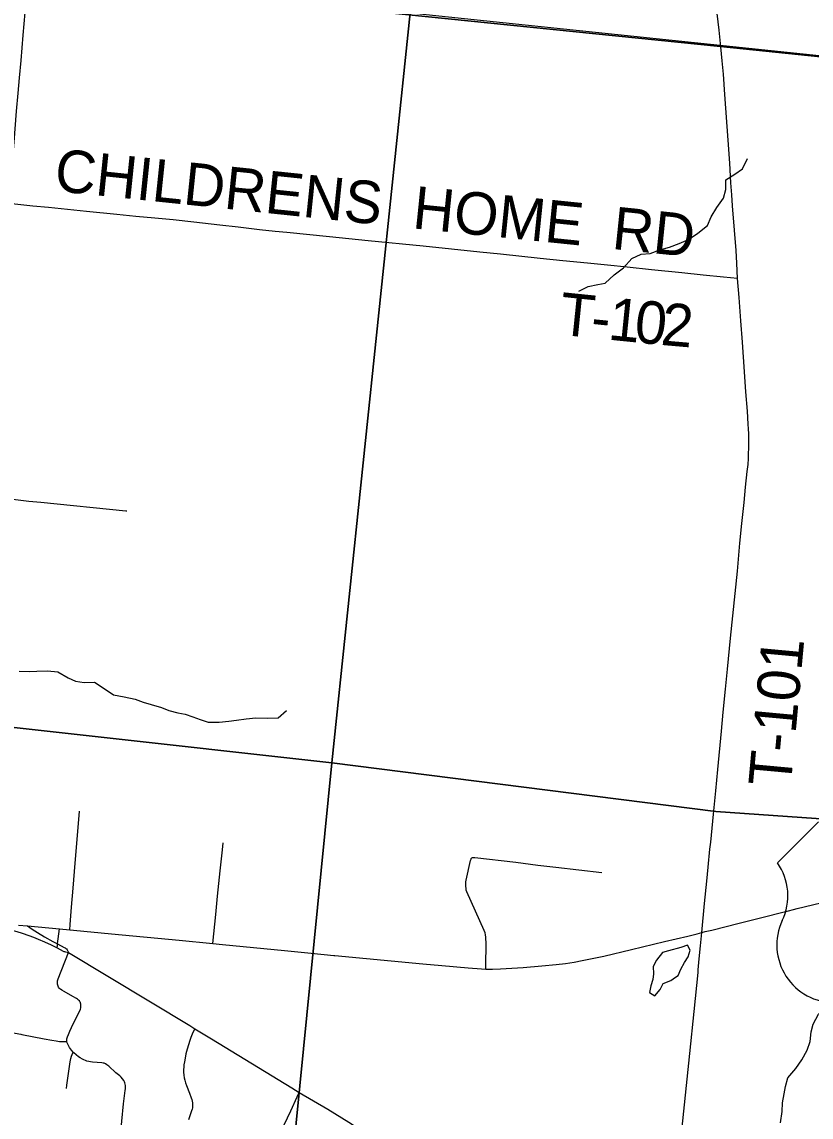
# Model space of a CAD drawing. Extents: x 0 to 1067, y 0 to 440.
# Drawn here: x 445.6 to 508.9, y 79.3 to 167.1 of the extents above; entities that cross this region are included whole.
import ezdxf

# ---------------------------------------------------------------- set-up
doc = ezdxf.new("R2010")
doc.units = 0
for name, color, linetype in [('GM_X_City_Street', 7, 'Continuous'), ('GM_X_Minor_Lake', 7, 'Continuous'), ('GM_X_Minor_River', 7, 'Continuous'), ('GM_X_Section', 7, 'Continuous'), ('GM_X_State_Route', 7, 'Continuous'), ('GM_X_Township_Road', 7, 'Continuous'), ('GM_X_Township_Road_Text', 7, 'Continuous'), ('GM_X_US_Route', 7, 'Continuous'), ('GM_X_US_Shield', 7, 'Continuous')]:
    doc.layers.add(name, color=color, linetype=linetype)

msp = doc.modelspace()

# ---------------------------------------------------------------- linework, layer by layer
at = {"layer": 'GM_X_City_Street'}
for points in [[(443.831, 125.541), (443.87, 125.958), (443.98, 127.147), (444.089, 128.111), (444.125, 128.52), (444.151, 128.63), (444.181, 128.697), (444.225, 128.757), (444.281, 128.805), (444.382, 128.851), (444.492, 128.862), (445.124, 128.802), (446.199, 128.688), (447.163, 128.585), (453.978, 127.908), (454.048, 127.901)], [(449.481, 94.317), (449.517, 94.753), (449.629, 96.127), (449.755, 97.649), (449.866, 98.986), (450.265, 103.821)], [(460.948, 93.213), (461.182, 95.554), (461.318, 97.004), (461.528, 99.046), (461.717, 100.716), (461.778, 101.284)], [(482.826, 91.173), (482.837, 91.669), (482.866, 92.972), (482.857, 93.361), (482.848, 93.552), (482.835, 93.733), (482.808, 93.914), (482.77, 94.066), (482.702, 94.25), (481.31, 97.348), (481.269, 97.492), (481.247, 97.633), (481.229, 97.823), (481.225, 97.987), (481.238, 98.15), (481.258, 98.293), (481.62, 99.866), (481.65, 99.972), (481.671, 100.032), (481.707, 100.083), (481.761, 100.112), (481.831, 100.123), (481.963, 100.113), (485.246, 99.742), (486.993, 99.498), (488.457, 99.335), (490.302, 99.13), (492.137, 98.913)], [(453.523, 77.598), (453.802, 80.367), (453.876, 80.996), (453.926, 81.438), (453.937, 81.577), (453.944, 81.759), (453.94, 81.849), (453.925, 81.954), (453.903, 82.05), (453.869, 82.14), (453.824, 82.225), (453.72, 82.369), (453.597, 82.509), (453.496, 82.601), (453.184, 82.859), (452.613, 83.382), (452.461, 83.492), (452.335, 83.574), (452.23, 83.615), (452.152, 83.634), (452.043, 83.65), (451.678, 83.677), (451.301, 83.702), (451.135, 83.723), (450.997, 83.753), (450.859, 83.794), (450.746, 83.834), (450.61, 83.894), (450.502, 83.945), (450.315, 84.051), (450.182, 84.145), (450.001, 84.283), (449.806, 84.456), (449.754, 84.518), (449.627, 84.664), (449.468, 84.886), (449.322, 85.138), (449.276, 85.249), (449.253, 85.365), (449.246, 85.477), (449.256, 85.568), (449.302, 85.734), (449.377, 85.931), (449.488, 86.204), (449.61, 86.482), (450.331, 87.955), (450.36, 88.052), (450.374, 88.159), (450.377, 88.294), (450.368, 88.369), (450.353, 88.428), (450.33, 88.495), (450.299, 88.546), (450.256, 88.618), (450.192, 88.685), (450.114, 88.748), (450.022, 88.811), (449.738, 88.975), (449.024, 89.369), (448.835, 89.488), (448.739, 89.55), (448.684, 89.594), (448.635, 89.643), (448.579, 89.721), (448.546, 89.795), (448.52, 89.873), (448.503, 89.961), (448.491, 90.081), (448.497, 90.172), (448.511, 90.238), (448.556, 90.387), (449.373, 92.511)], [(427.54, 87.969), (428.165, 87.921), (429.724, 87.787), (440.527, 86.741), (441.537, 86.636), (441.88, 86.594), (442.641, 86.476), (443.587, 86.308), (445.546, 85.942), (445.63, 85.926), (447.436, 85.576), (448.043, 85.462), (448.382, 85.406), (448.645, 85.376), (448.887, 85.355), (449.253, 85.365)], [(459.502, 86.39), (459.377, 86.14), (459.288, 85.945), (459.191, 85.695), (459.107, 85.432), (458.895, 84.756), (458.794, 84.367), (458.72, 84.016), (458.67, 83.739), (458.635, 83.493), (458.618, 83.295), (458.611, 83.122), (458.607, 82.909), (458.623, 82.676), (458.658, 82.455), (458.698, 82.258), (458.754, 82.057), (458.839, 81.835), (459.086, 81.21), (459.213, 80.861), (459.258, 80.717), (459.296, 80.568), (459.313, 80.453), (459.326, 80.312), (459.322, 80.168), (459.313, 80.048), (459.296, 79.951), (459.252, 79.798), (459.011, 79.093)], [(449.214, 81.604), (449.239, 81.857), (449.34, 82.611), (449.517, 83.741), (449.568, 84.004), (449.617, 84.182), (449.663, 84.315), (449.754, 84.518)], [(466.362, 78.057), (467.214, 79.797), (467.72, 80.916), (467.885, 81.28)]]:
    msp.add_lwpolyline(points, dxfattribs=at)
at = {"layer": 'GM_X_Minor_Lake'}
for points in [[(498.051, 90.518), (498.25, 90.646), (498.481, 91.167), (498.758, 91.688), (499.057, 92.141), (499.22, 92.686), (498.997, 93.097), (498.473, 92.896), (497.472, 92.631), (496.994, 92.499)], [(496.994, 92.499), (496.512, 91.888), (496.258, 91.367), (496.276, 90.798), (496.227, 90.343), (496.064, 89.821), (495.969, 89.299), (496.398, 89.023), (496.811, 89.542), (497.042, 90.018), (497.657, 90.264), (498.051, 90.518)]]:
    msp.add_lwpolyline(points, dxfattribs=at)
at = {"layer": 'GM_X_Minor_River'}
for points in [[(490.28, 145.516), (491.033, 145.896), (491.806, 146.05), (492.397, 146.158), (493.129, 146.812), (493.86, 147.375), (494.547, 148.121), (495.299, 148.479), (496.003, 148.518), (496.777, 148.831), (497.551, 149.029), (498.325, 149.342), (499.077, 149.654), (499.83, 150.171), (500.607, 150.779), (500.908, 151.482), (501.345, 152.229), (501.896, 152.953), (502.083, 153.657), (502.09, 154.43), (502.797, 154.902), (503.414, 155.33), (503.806, 156.146)], [(445.424, 115.045), (446.218, 115.016), (446.831, 115.056), (447.694, 115.072), (448.533, 114.997), (449.347, 114.513), (449.935, 114.236), (450.637, 114.139), (451.455, 114.178), (452.245, 113.648), (452.99, 113.165), (453.829, 112.999), (454.713, 112.81)], [(454.713, 112.81), (455.369, 112.577), (456.003, 112.368), (456.841, 112.133), (457.429, 111.901), (458.154, 111.714), (458.743, 111.595), (459.354, 111.386), (459.943, 111.176), (460.577, 110.966), (461.462, 110.959), (462.234, 111.044), (462.848, 111.131), (463.621, 111.238), (464.393, 111.3), (465.369, 111.27), (466.187, 111.309), (466.85, 111.895)], [(506.46, 78.839), (506.581, 79.748), (506.633, 80.453), (506.752, 81.158), (506.848, 81.748), (507.058, 82.452), (507.677, 83.198), (508.159, 83.899), (508.597, 84.669), (508.83, 85.373), (508.927, 86.145), (509.091, 86.758), (509.506, 87.551), (510.033, 88.139), (510.792, 89.384)]]:
    msp.add_lwpolyline(points, dxfattribs=at)
at = {"layer": 'GM_X_Section'}
for points in [[(476.775, 167.814), (470.491, 107.701), (410.18, 114.397), (415.565, 173.729)], [(537.229, 161.525), (531.153, 101.704), (501.276, 103.799), (470.491, 107.701), (476.775, 167.814)], [(410.18, 114.397), (470.491, 107.701), (464.499, 47.289), (404.583, 52.958)], [(470.491, 107.701), (501.276, 103.799), (531.153, 101.704), (525.387, 41.267), (464.499, 47.289)]]:
    msp.add_lwpolyline(points, close=True, dxfattribs=at)
at = {"layer": 'GM_X_State_Route'}
for points in [[(442.198, 94.991), (443.688, 94.605), (444.446, 94.408), (445.242, 94.187), (445.66, 94.058), (446.189, 93.871), (446.583, 93.724), (446.937, 93.577), (447.445, 93.363), (448.001, 93.109), (448.465, 92.863), (448.949, 92.606), (449, 92.585), (449.054, 92.568), (449.144, 92.547), (449.373, 92.511)], [(446.083, 94.627), (446.476, 94.373), (446.904, 94.095), (447.452, 93.751), (448.121, 93.376), (448.505, 93.18), (449.037, 92.908), (449.105, 92.869), (449.177, 92.821), (449.207, 92.799), (449.274, 92.712), (449.307, 92.652), (449.373, 92.511)], [(448.465, 92.863), (448.489, 93.049), (448.505, 93.18), (448.535, 93.417), (448.555, 93.59), (448.667, 94.394)], [(449.373, 92.511), (459.098, 86.637), (459.502, 86.39), (460.848, 85.568), (467.278, 81.641), (467.885, 81.28), (470.165, 79.93), (471.845, 78.896), (472.387, 78.562), (474.975, 76.922)]]:
    msp.add_lwpolyline(points, dxfattribs=at)
at = {"layer": 'GM_X_Township_Road'}
for points in [[(445.658, 165.009), (445.743, 166.03), (445.905, 167.849), (446.099, 169.926), (446.169, 170.766)], [(446.156, 170.798), (501.66, 165.116), (539, 161.279)], [(539, 161.279), (501.66, 165.116), (446.156, 170.798)], [(501.674, 165.084), (501.536, 166.424), (501.38, 167.757)], [(503.019, 146.522), (502.967, 147.768), (502.898, 148.772), (502.771, 150.408), (502.619, 152.339), (502.552, 153.231), (502.486, 154.198), (502.39, 155.761), (502.258, 157.621), (502.004, 161.266), (501.883, 162.902), (501.788, 163.978), (501.674, 165.084)], [(444.604, 152.535), (444.714, 153.737), (444.796, 154.631), (444.87, 155.56), (445.019, 157.454), (445.222, 159.942), (445.352, 161.389), (445.459, 162.614), (445.573, 163.988), (445.658, 165.009)], [(457.777, 151.218), (456.296, 151.357), (454.776, 151.503), (453.257, 151.655), (450.813, 151.91), (447.778, 152.212), (446.52, 152.337), (444.604, 152.535)], [(503.019, 146.522), (501.879, 146.635), (500.261, 146.795), (498.544, 146.975), (496.127, 147.23), (494.179, 147.435), (492.584, 147.59), (490.989, 147.751), (489.022, 147.947), (487.205, 148.139), (484.015, 148.464), (482.346, 148.633), (477.821, 149.108), (473.41, 149.555), (470.291, 149.876), (466.882, 150.218), (465.955, 150.305), (464.695, 150.439), (462.991, 150.628), (461.508, 150.788), (459.417, 151.029), (457.777, 151.218)], [(501.858, 111.761), (502.051, 113.619), (502.216, 115.217), (502.464, 117.701), (503.003, 123.078), (503.212, 125.304), (503.365, 126.898), (503.536, 128.564), (503.662, 129.787), (503.794, 131.051), (503.857, 131.625), (503.892, 132.093), (503.9, 132.415), (503.92, 133.008), (503.928, 133.505), (503.913, 134.084), (503.885, 134.483), (503.862, 134.853), (503.81, 135.893), (503.687, 137.448), (503.573, 139.046), (503.41, 141.417), (503.292, 143.141), (503.152, 144.999), (503.019, 146.522)], [(500.807, 100.771), (500.866, 101.353), (501.09, 103.58), (501.273, 105.458), (501.44, 107.18), (501.719, 110.235), (501.858, 111.761)], [(500.151, 94.098), (500.378, 96.418), (500.552, 98.21), (500.662, 99.35), (500.807, 100.771)], [(499.868, 91.108), (499.948, 91.977), (500.049, 93.033), (500.151, 94.098)], [(497.055, 63.501), (497.149, 64.342), (497.276, 65.603), (497.544, 68.161), (497.763, 70.311), (498.067, 73.389), (498.502, 77.727), (499.187, 84.4), (499.541, 87.773), (499.847, 90.888), (499.868, 91.108)]]:
    msp.add_lwpolyline(points, dxfattribs=at)
at = {"layer": 'GM_X_US_Route'}
for p, q in [((500.151, 94.098), (500.432, 94.169)), ((461.726, 93.138), (466.691, 92.653))]:
    msp.add_line(p, q, dxfattribs=at)
for points in [[(506.761, 95.755), (506.819, 95.769), (507.805, 96.013), (510.357, 96.649), (512.151, 97.106), (513.89, 97.525), (516.902, 98.232), (518.787, 98.684), (523.075, 99.671), (525.47, 100.231), (527.467, 100.694), (528.81, 101.006), (529.574, 101.171), (530.453, 101.317), (531.228, 101.41), (531.894, 101.444), (532.561, 101.438), (533.452, 101.383), (535.193, 101.219), (538.084, 100.946), (539, 100.86)], [(500.432, 94.169), (500.952, 94.301), (503.146, 94.855), (504.432, 95.174), (504.97, 95.312), (506.761, 95.755)], [(445.378, 94.69), (446.083, 94.627), (448.667, 94.394), (449.481, 94.317), (449.779, 94.289)], [(449.779, 94.289), (452.818, 94), (458.258, 93.476), (460.948, 93.213), (461.726, 93.138)], [(482.826, 91.173), (482.892, 91.17), (483.372, 91.164), (484.012, 91.18), (485.833, 91.301), (487.318, 91.416), (488.465, 91.531), (489.219, 91.622), (489.915, 91.727), (490.561, 91.852), (492.3, 92.206), (494.511, 92.728), (497.168, 93.376), (499.018, 93.82), (499.792, 94.004), (500.151, 94.098)], [(466.691, 92.653), (468.844, 92.444), (470.659, 92.267)], [(470.659, 92.267), (470.718, 92.261), (477.782, 91.591), (479.298, 91.458)], [(479.298, 91.458), (481.421, 91.272), (482.496, 91.189), (482.826, 91.173)]]:
    msp.add_lwpolyline(points, dxfattribs=at)
at = {"layer": 'GM_X_US_Shield'}
msp.add_line((509.514, 102.985), (506.218, 99.689), dxfattribs=at)
for centre, start, end in [((502.438, 97.042), 334.54712, 35.00093), ((510.781, 93.097), 154.83192, 270.63826)]:
    msp.add_arc(centre, 4.614, start, end, dxfattribs=at)

# ---------------------------------------------------------------- texts
at = {"layer": 'GM_X_Township_Road_Text'}
for s, height, rotation, p in [('CHILDRENS', 3.4091, 354.04672, (448.163, 153.557)), ('HOME', 3.4091, 354.15114, (476.876, 150.556)), ('RD', 3.4091, 354.09322, (492.867, 148.906)), ('T', 3.409, 354.16574, (488.627, 142.036)), ('1', 3.409, 354.21113, (492.56, 141.635)), ('0', 3.409, 354.34932, (494.658, 141.422)), ('2', 3.409, 354.9987, (496.79, 141.211)), ('-', 3.409, 354.17907, (491.165, 141.777)), ('T-101', 3.4091, 84.73299, (507.272, 105.701))]:
    msp.add_text(s, height=height, rotation=rotation, dxfattribs=at).set_placement(p)

doc.saveas('drawing.dxf')
